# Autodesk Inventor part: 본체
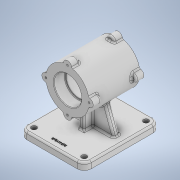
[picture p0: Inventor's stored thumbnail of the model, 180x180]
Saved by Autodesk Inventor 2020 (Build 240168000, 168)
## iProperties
Created: 2022-11
Part Number: 본체
Material: 일반
Document SubType Name: Modeling
Designer: owner
Density: 1 g/cm^3
Appearance: 기본값
Mass: 449.313 g
Surface Area: 796.963 cm^2
Volume: 449.313 cm^3
Author: owner
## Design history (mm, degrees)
sketch "스케치1"
  geometry: C1 r 37 at (0, 0); 1 further point
  constraints: 1 centre point, 1 coincident
  dimensions: "d0" = 74 diameter of C1
extrude "돌출1" new body sketch "스케치1" distance "d1" = 87; taper "d2" = 0 deg
sketch "스케치2"
  geometry: C1 r 23.5 at (0, 0); 1 further point
  constraints: 1 centre point, 1 coincident
  dimensions: "d3" = 47 diameter of C1
extrude "돌출2" cut sketch "스케치2" distance "d4" = 19; taper "d5" = 0 deg
sketch "스케치3"
  geometry: C1 r 7 at (0, 37); 2 further points
  constraints: 1 centre point, 1 vertical alignment, 1 other
  dimensions: "d6" = 14 diameter of C1
extrude "돌출3" join sketch "스케치3" distance "d7" = 14; taper "d8" = 0 deg
sketch "스케치4"
  geometry: C1 r 7 at (-37, 0); C2 r 7 at (0, -37); C3 r 7 at (37, 0); A1 r 37 centre (0, 0) between (-37, 0) and (0, -37) reference; 1 further point
  constraints: 3 centre point, 3 point on circle
  dimensions: "d9" = 14 diameter of C1; "d10" = 14 diameter of C2; "d11" = 14 diameter of C3
extrude "돌출4" join sketch "스케치4" distance "d12" = 14; taper "d13" = 0 deg
sketch "스케치5"
  geometry: C1 r 7 at (-37, 0); A1 r 37 centre (0, 0) between (-6.969, 36.338) and (-6.969, -36.338) reference; 1 further point
  constraints: 1 centre point, 1 point on circle
  dimensions: "d14" = 14 diameter of C1
extrude "돌출5" join sketch "스케치5" distance "d15" = 14; taper "d16" = 0 deg
sketch "스케치6"
  geometry: C1 r 23.5 at (0, 0); 1 further point
  constraints: 1 centre point, 1 coincident
  dimensions: "d17" = 47 diameter of C1
extrude "돌출6" cut sketch "스케치6" distance "d18" = 19; taper "d19" = 0 deg
sketch "스케치7"
  geometry: C1 r 7 at (0, 37); C2 r 7 at (-37, 0); C3 r 7 at (0, -37); C4 r 7 at (37, 0); A1 r 37 centre (0, 0) between (0, 37) and (-37, 0) reference; A2 r 7 centre (37, 0) between (36.338, -6.969) and (36.338, 6.969) reference; 3 further points
  constraints: 4 centre point, 3 point on circle, 1 coincident
  dimensions: "d20" = 14 diameter of C1; "d21" = 14 diameter of C2; "d22" = 14 diameter of C3; "d23" = 14 diameter of C4
extrude "돌출7" join sketch "스케치7" distance "d24" = 14; taper "d25" = 0 deg
sketch "스케치8"
  geometry: C1 r 21 at (0, 0); 1 further point
  constraints: 1 centre point, 1 coincident
  dimensions: "d26" = 42 diameter of C1
extrude "돌출8" cut sketch "스케치8" stored distance "d27" = 19; taper "d28" = 0 deg
sketch "스케치9"
  geometry: A1 r 7 centre (0, 37) between (6.969, 36.338) and (-6.969, 36.338) reference; 2 further points
  constraints: 1 coincident
hole "구멍1" sketch "스케치9" at (0, 37) diameter "d29" = 3.242; stored, may be unused: countersink angle "d33" = 90 deg, drill point angle "d35" = 118 deg; dims "d30" = 8, "d31" = 4, "d32" = 2, "d34" = 10
sketch "스케치10"
  geometry: C1 r 1.621 at (0, 37) reference; 2 further points
  constraints: 1 coincident
hole "구멍2" sketch "스케치10" at (0, 37) diameter "d39" = 3.242; stored, may be unused: countersink angle "d43" = 90 deg, drill point angle "d45" = 118 deg; dims "d40" = 8, "d41" = 4, "d42" = 2, "d44" = 10
node "작업 평면1"
node "작업 평면2"
sketch "스케치13"
  geometry: L1 (55, 26.5)-(-55, 26.5); L2 (-55, 26.5)-(-55, -103.5); L3 (-55, -103.5)-(55, -103.5); L4 (55, -103.5)-(55, 26.5); L5 (55, 26.5)-(-55, -103.5); L6 (-55, 26.5)-(55, -103.5); 4 further points
  constraints: 12 end point, 3 midpoint, 2 parallel, 1 horizontal, 1 perpendicular, 1 vertical alignment
  dimensions: "d67" = 110 distance of L3.end L2.end; "d68" = 130 distance of L2.end L1.end; "d69" = 43.5 vertical distance of point (25.568, -43.5) point (0, 0); "d70" = 70 distance from line of point (25.568, -43.5) L1
extrude "돌출10" join sketch "스케치13" distance "d71" = 12; taper "d72" = 0 deg
node "작업 평면3"
sketch "스케치17"
  geometry: L1 (-55, -26.5)-(55, -26.5) reference; L2 (-55, 103.5)-(-55, -26.5) reference; L3 (55, -26.5)-(55, 103.5) reference; L4 (55, 103.5)-(-55, 103.5) reference; 5 further points
  dimensions: "d99" = 12 distance from line of L1 point (-43, -14.5); "d100" = 12 distance from line of L2 point (-43, -14.5); "d101" = 12 distance from line of L3 point (43, -14.5); "d102" = 12 distance from line of L1 point (43, -14.5); "d104" = 12 distance from line of L4 point (43, 91.5); "d105" = 12 distance from line of L3 point (43, 91.5); "d106" = 12 distance from line of L4 point (-43, 91.5); "d107" = 12 distance from line of L2 point (-43, 91.5)
hole "구멍3" sketch "스케치17" at (43, -14.5), (43, 91.5), (-43, 91.5), (-43, -14.5) diameter "d108" = 9; stored, may be unused: countersink angle "d112" = 90 deg, drill point angle "d114" = 118 deg; dims "d109" = 24, "d110" = 4, "d111" = 2, "d113" = 32.3
node "작업 평면4"
sketch "스케치18"
  geometry: L1 (55, -70)-(-55, -70) reference; L2 (-25.336, -26.964)-(-41, -70); L3 (25.336, -26.964)-(41, -70); A1 r 37 centre (0, 0) between (-36.338, -6.969) and (-6.969, -36.338) reference; A2 r 37 centre (0, 0) between (6.969, -36.338) and (36.338, -6.969) reference; A3 r 37 centre (0, 0) between (-6.969, -36.338) and (6.969, -36.338) reference; 1 further point
  constraints: 4 end point, 2 point on circle, 2 point on line
  dimensions: "d116" = 110 deg angle of L1 L2; "d117" = 14 distance of L1.end L2.end; "d118" = 14 distance of L1.start L3.end; "d119" = 110 deg angle of L1 L3
extrude "돌출12" join sketch "스케치18" stored distance "d120" = 10; taper "d121" = 0 deg
sketch "스케치19"
  geometry: L1 (-37, -14)-(-37, -73) reference; L2 (-37, -23.5)-(-70, -23.5); L3 (-70, -103.5)-(-70, 26.5) reference; L4 (-37, -63.5)-(-70, -63.5); L5 (-70, -38.5)-(-26.964, -38.5) reference; L6 (-26.964, -48.5)-(-70, -48.5) reference; 1 further point
  constraints: 4 end point, 2 horizontal, 2 point on line
  dimensions: "d122" = 15 distance between parallel lines of L5 L2; "d123" = 15 distance between parallel lines of L6 L4
feature "리브3" sketch "스케치19" dims "d124" = 1, "d125" = 10, "d126" = 0, "d127" = 0, "d128" = 1, "d129" = 1
sketch "스케치20"
  geometry: L1 (-37, -14)-(-37, -73) reference; L2 (-37, -63.5)-(-70, -63.5); L3 (-70, 26.5)-(-70, -103.5) reference; L4 (-26.964, -48.5)-(-70, -48.5) reference; 1 further point
  constraints: 2 end point, 2 point on line, 1 horizontal
  dimensions: "d130" = 15 distance between parallel lines of L4 L2
feature "리브4" sketch "스케치20" dims "d131" = 1, "d132" = 10, "d133" = 0, "d134" = 0, "d135" = 1, "d136" = 1
fillet "모깎기4" dims "d137" = 3
fillet "모깎기5" dims "d138" = 12
fillet "모깎기6" dims "d139" = 3
fillet "모깎기7" dims "d140" = 3
fillet "모깎기8" dims "d141" = 3
sketch "스케치21"
  geometry: L1 (-6.889, 0)-(6.889, 0) reference; L2 (-43, -26.5)-(43, -26.5) reference; 3 further points
  constraints: 1 midpoint, 1 vertical alignment, 1 other
  dimensions: "d142" = 12 distance from line of L2 point (0, -14.5)
feature "엠보싱1" sketch "스케치21" dims "d143" = 0.5, "d144" = 0
fillet "모깎기9" dims "d145" = 1
chamfer "모따기1" distance "d146" = 1; stored, may be unused: second distance "d147" = 2, angle "d148" = 45 deg
node "솔리드1"
pattern_circular "원형 패턴1" dims angle "d37" = 360 deg
pattern_circular "원형 패턴2" dims angle "d47" = 360 deg
feature "A9D066F2-1C7D-4E18-AEED-F7BC21143FA4" dims "d108" = 9, "d109" = 24, "d110" = 4, "d111" = 2, "d112" = 90 deg, "d113" = 32.3, "d114" = 118 deg
other parameters: "d49" = -82, "d54" = -43.5, "d73" = -43.5, "d115" = -43.5
